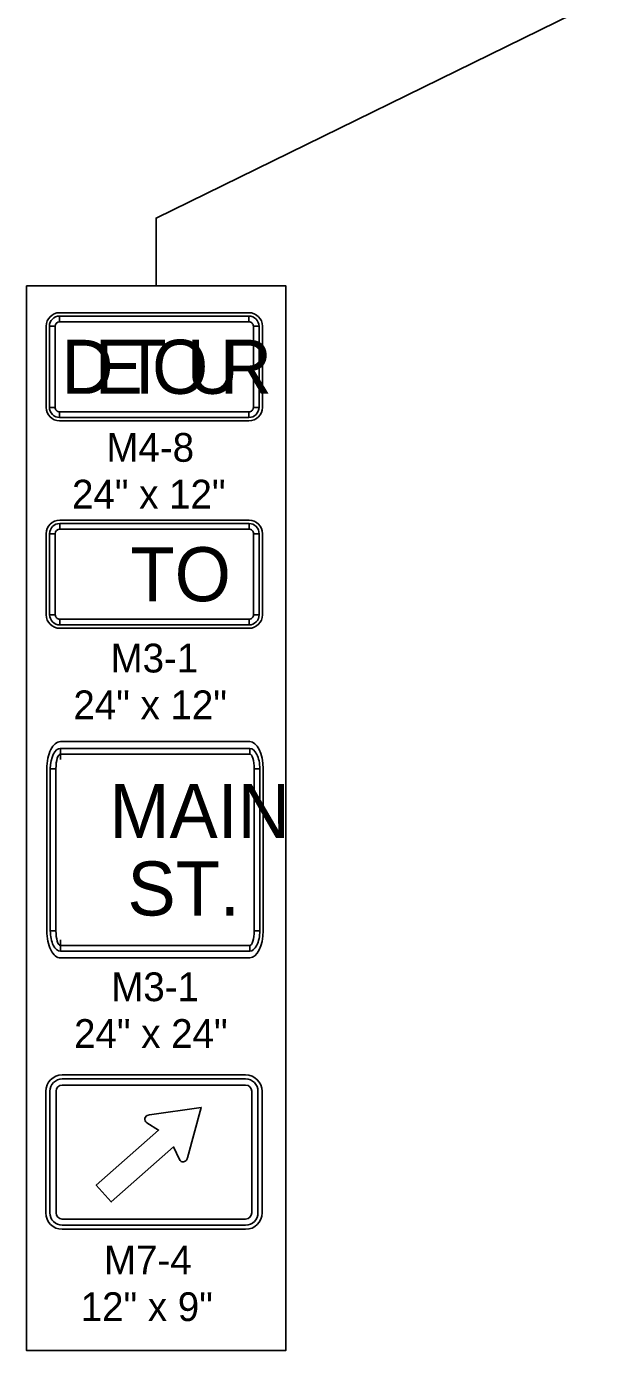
# Model space of a CAD drawing. Extents: x 10133 to 81668, y 6132 to 11018.
# Drawn here: x 11551.6 to 11712.8, y 8749.2 to 9117.3 of the extents above; entities that cross this region are included whole.
import ezdxf

# ---------------------------------------------------------------- set-up
doc = ezdxf.new("R2010")
doc.units = 0
for name, color, linetype in [('dsnTextFinalPlan', 7, 'Continuous'), ('Level 10', 7, 'Continuous'), ('Level 5', 7, 'Continuous')]:
    doc.layers.add(name, color=color, linetype=linetype)

msp = doc.modelspace()

# ---------------------------------------------------------------- linework, layer by layer
at = {"layer": 'dsnTextFinalPlan'}
for p, q in [((11612.48, 8825.81), (11561.51, 8825.81)), ((11556.93, 8821.23), (11556.93, 8787.44)), ((11617.06, 8787.44), (11617.06, 8821.23)), ((11561.51, 8782.86), (11612.48, 8782.86))]:
    msp.add_line(p, q, dxfattribs=at)
for points in [[(11587.6, 9045.25), (11587.6, 9064.06), (11712.82, 9125.45)], [(11585.78, 8814.67), (11600.14, 8816.74), (11596.29, 8802.76)], [(11594.07, 8802.25), (11592.45, 8805.76), (11575.12, 8790.47), (11570.97, 8795.18), (11588.29, 8810.47), (11585, 8812.5)]]:
    msp.add_lwpolyline(points, dxfattribs=at)
msp.add_lwpolyline([(11551.57, 9045.25), (11623.63, 9045.25), (11623.63, 8749.15), (11551.57, 8749.15)], close=True, dxfattribs=at)
msp.add_lwpolyline([(11551.57, 9045.25), (11623.63, 9045.25), (11623.63, 8749.15), (11551.57, 8749.15)], close=True, dxfattribs=at)
for centre, radius, start, end in [((11561.51, 8821.23), 4.58, 90, 180), ((11612.48, 8821.23), 4.58, 360, 90), ((11585.62, 8813.48), 1.16, 98.0346, 237.3927), ((11569.25, 8929.45), 115.96, 278.0346, 278.1951), ((11595.1, 8802.73), 1.14, 205.4546, 344.7341), ((11708.07, 8771.9), 115.96, 164.5667, 164.7341), ((11561.51, 8787.44), 4.58, 180, 270), ((11612.48, 8787.44), 4.58, 270, 0)]:
    msp.add_arc(centre, radius, start, end, dxfattribs=at)
at = {"layer": 'Level 10'}
for p, q in [((11560.77, 9037.74), (11613.39, 9037.74)), ((11560.77, 9035.23), (11560.77, 9036.8)), ((11613.39, 9036.8), (11613.39, 9035.23)), ((11557.02, 9011.43), (11557.02, 9033.98)), ((11557.96, 9033.98), (11559.52, 9033.98)), ((11614.64, 9033.98), (11616.21, 9033.98)), ((11617.14, 9033.98), (11617.14, 9011.43)), ((11559.52, 9011.43), (11557.96, 9011.43)), ((11560.77, 9008.62), (11560.77, 9010.18)), ((11613.39, 9010.18), (11613.39, 9008.62)), ((11616.21, 9011.43), (11614.64, 9011.43)), ((11613.39, 9007.68), (11560.77, 9007.68)), ((11560.82, 8980.05), (11613.43, 8980.05)), ((11557.06, 8953.75), (11557.06, 8976.3)), ((11558, 8976.3), (11559.57, 8976.3)), ((11560.82, 8977.55), (11560.82, 8979.11)), ((11613.43, 8979.11), (11613.43, 8977.55)), ((11614.69, 8976.3), (11616.25, 8976.3)), ((11617.19, 8976.3), (11617.19, 8953.75)), ((11559.57, 8953.75), (11558, 8953.75)), ((11560.82, 8950.93), (11560.82, 8952.5)), ((11613.43, 8952.5), (11613.43, 8950.93)), ((11616.25, 8953.75), (11614.69, 8953.75)), ((11613.43, 8949.99), (11560.82, 8949.99)), ((11561.01, 8918.47), (11613.62, 8918.47)), ((11561.01, 8913.46), (11561.01, 8916.59)), ((11613.62, 8916.59), (11613.62, 8915.03)), ((11557.25, 8865.86), (11557.25, 8910.95)), ((11558.19, 8910.95), (11559.76, 8910.95)), ((11614.88, 8910.95), (11616.44, 8910.95)), ((11617.38, 8910.95), (11617.38, 8865.86)), ((11559.76, 8865.86), (11558.19, 8865.86)), ((11616.44, 8865.86), (11614.88, 8865.86)), ((11561.01, 8860.22), (11561.01, 8863.35)), ((11613.62, 8861.79), (11613.62, 8860.22)), ((11613.62, 8858.34), (11561.01, 8858.34)), ((11612.48, 8824.66), (11561.51, 8824.66)), ((11612.48, 8822.94), (11561.51, 8822.94)), ((11558.08, 8821.23), (11558.08, 8787.44)), ((11559.8, 8821.23), (11559.8, 8787.44)), ((11614.2, 8787.44), (11614.2, 8821.23)), ((11615.92, 8787.44), (11615.92, 8821.23)), ((11561.51, 8785.72), (11612.48, 8785.72)), ((11561.51, 8784), (11612.48, 8784))]:
    msp.add_line(p, q, dxfattribs=at)
for points in [[(11613.39, 9036.8), (11560.77, 9036.8), (11560.77, 9035.23), (11613.39, 9035.23), (11613.39, 9036.8)], [(11557.96, 9033.98), (11557.96, 9011.43), (11559.52, 9011.43), (11559.52, 9033.98), (11557.96, 9033.98)], [(11616.21, 9011.43), (11616.21, 9033.98), (11614.64, 9033.98), (11614.64, 9011.43), (11616.21, 9011.43)], [(11560.77, 9008.62), (11613.39, 9008.62), (11613.39, 9010.18), (11560.77, 9010.18), (11560.77, 9008.62)], [(11558, 8976.3), (11558, 8953.75), (11559.57, 8953.75), (11559.57, 8976.3), (11558, 8976.3)], [(11613.43, 8979.11), (11560.82, 8979.11), (11560.82, 8977.55), (11613.43, 8977.55), (11613.43, 8979.11)], [(11616.25, 8953.75), (11616.25, 8976.3), (11614.69, 8976.3), (11614.69, 8953.75), (11616.25, 8953.75)], [(11560.82, 8950.93), (11613.43, 8950.93), (11613.43, 8952.5), (11560.82, 8952.5), (11560.82, 8950.93)], [(11613.62, 8916.59), (11561.01, 8916.59), (11561.01, 8915.03), (11613.62, 8915.03), (11613.62, 8916.59)], [(11558.19, 8910.95), (11558.19, 8865.86), (11559.76, 8865.86), (11559.76, 8910.95), (11558.19, 8910.95)], [(11616.44, 8865.86), (11616.44, 8910.95), (11614.88, 8910.95), (11614.88, 8865.86), (11616.44, 8865.86)], [(11561.01, 8860.22), (11613.62, 8860.22), (11613.62, 8861.79), (11561.01, 8861.79), (11561.01, 8860.22)]]:
    msp.add_lwpolyline(points, close=True, dxfattribs=at)
for centre, radius, start, end in [((11560.77, 9033.98), 3.76, 90, 180), ((11560.77, 9033.98), 2.82, 90.0002, 179.9998), ((11560.77, 9033.98), 1.25, 90.0002, 179.9998), ((11613.39, 9033.98), 3.76, 0, 90), ((11613.39, 9033.98), 2.82, 0, 90.0002), ((11613.39, 9033.98), 1.25, 0, 90.0002), ((11560.77, 9011.43), 3.76, 180, 270), ((11560.77, 9011.43), 2.82, 179.9998, 270.0001), ((11560.77, 9011.43), 1.25, 179.9998, 270.0001), ((11613.39, 9011.43), 2.82, 270.0001, 0.0003), ((11613.39, 9011.43), 1.25, 270.0001, 0.0003), ((11613.39, 9011.43), 3.76, 270, 359.9911), ((11560.82, 8976.3), 3.76, 90, 180), ((11613.43, 8976.3), 3.76, 0, 90), ((11560.82, 8976.3), 2.82, 90.0002, 179.9998), ((11560.82, 8976.3), 1.25, 90.0002, 179.9998), ((11613.43, 8976.3), 2.82, 0, 90.0002), ((11613.43, 8976.3), 1.25, 0, 90.0002), ((11560.82, 8953.75), 3.76, 180, 270), ((11560.82, 8953.75), 2.82, 179.9998, 270.0001), ((11560.82, 8953.75), 1.25, 179.9998, 270.0001), ((11613.43, 8953.75), 2.82, 270.0001, 0.0003), ((11613.43, 8953.75), 1.25, 270.0001, 0.0003), ((11613.43, 8953.75), 3.76, 270, 359.9911), ((11561.51, 8821.23), 3.44, 90, 180), ((11561.51, 8821.23), 1.72, 90, 180), ((11612.48, 8821.23), 3.44, 0, 90), ((11612.48, 8821.23), 1.72, 0, 90), ((11561.51, 8787.44), 3.44, 180, 270), ((11561.51, 8787.44), 1.72, 180, 270), ((11612.48, 8787.44), 3.44, 270, 360), ((11612.48, 8787.44), 1.72, 270, 0)]:
    msp.add_arc(centre, radius, start, end, dxfattribs=at)
for centre, major_axis, ratio, start_param, end_param in [((11561.01, 8910.95), (0, 7.52), 0.5, 6.283185, 7.853982), ((11613.62, 8910.95), (0, 7.52), 0.5, 4.712389, 6.283185), ((11561.01, 8910.95), (0, 5.64), 0.5, 0.000004, 1.570794), ((11561.01, 8910.95), (0, 4.07), 0.307692, 0.000004, 1.570794), ((11613.62, 8910.95), (0, 5.64), 0.5, 4.712389, 6.283189), ((11613.62, 8910.95), (0, 4.07), 0.307692, 4.712389, 6.283189), ((11561.01, 8865.86), (0, 7.52), 0.5, 1.570796, 3.141593), ((11561.01, 8865.86), (0, 5.64), 0.5, 1.570794, 3.141594), ((11561.01, 8865.86), (0, 4.07), 0.307692, 1.570794, 3.141594), ((11613.62, 8865.86), (0, 5.64), 0.5, 3.141594, 4.712394), ((11613.62, 8865.86), (0, 4.07), 0.307692, 3.141594, 4.712394), ((11613.62, 8865.86), (0, 7.52), 0.5, 3.141593, 4.712234)]:
    msp.add_ellipse(centre, major_axis=major_axis, ratio=ratio, start_param=start_param, end_param=end_param, dxfattribs=at)

# ---------------------------------------------------------------- texts
for s, height, p in [('D', 15.03, (11561.26, 9015.19)), ('E', 15.03, (11570.5, 9015.19)), ('T', 15.03, (11578.28, 9015.19)), ('O', 15.03, (11586.48, 9015.19)), ('U', 15.03, (11596.08, 9015.19)), ('R', 15.03, (11605.31, 9015.19)), ('TO', 15.032, (11580.49, 8957.51)), ('MAIN', 15.032, (11574.58, 8891.66)), ('ST.', 15.032, (11579.63, 8870.12))]:
    msp.add_text(s, height=height, dxfattribs=at).set_placement(p)
at = {"layer": 'Level 5'}
for s, p in [('M4-8', (11573.78, 8996.29)), ('24" x 12"', (11564.23, 8983.29)), ('M3-1', (11574.95, 8937.7)), ('24" x 12"', (11564.61, 8924.7)), ('M3-1', (11575.14, 8846.3)), ('24" x 24"', (11564.8, 8833.3)), ('M7-4', (11573.11, 8770.35)), ('12" x 9"', (11566.64, 8757.35))]:
    msp.add_text(s, height=8, dxfattribs=at).set_placement(p)

doc.saveas('drawing.dxf')
